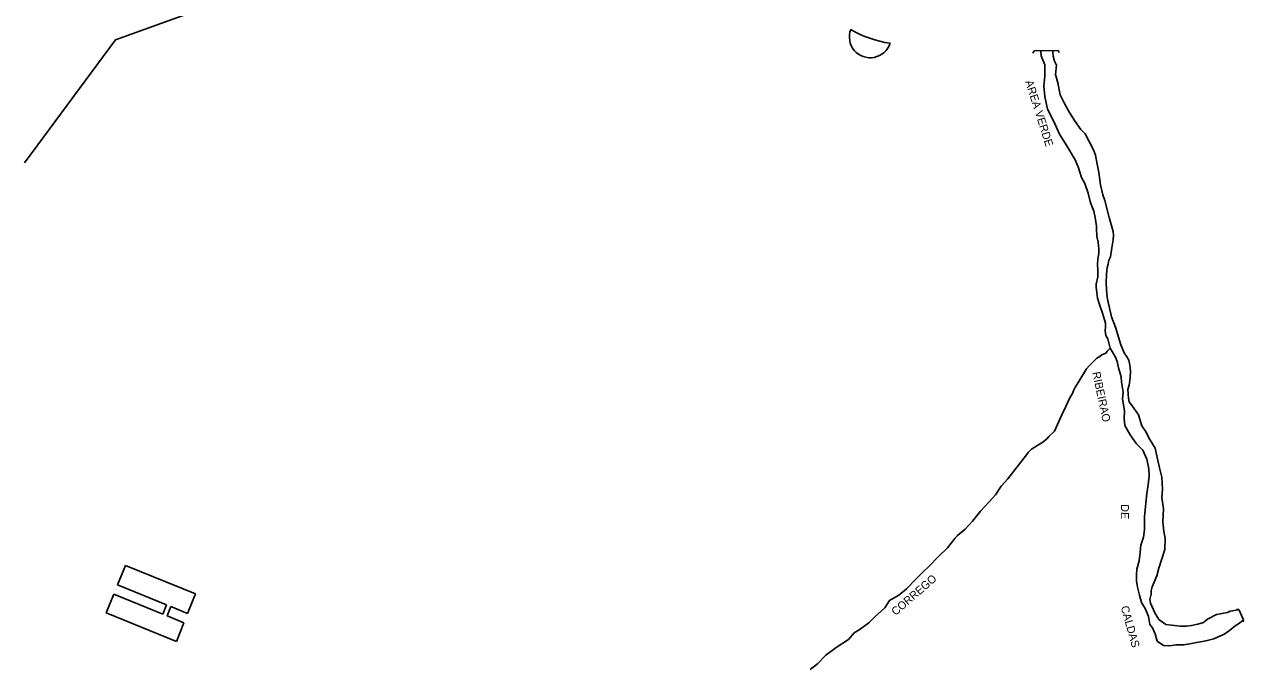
# Model space of a CAD drawing. Extents: x 325899 to 363134, y 7578590 to 7592502.
# Drawn here: x 338159 to 338768, y 7587778 to 7588098 of the extents above; entities that cross this region are included whole.
import ezdxf

# ---------------------------------------------------------------- set-up
doc = ezdxf.new("R2010")
doc.units = 0
for name, color, linetype in [('EDIFEXISTENT', 7, 'Continuous'), ('EDIFIDENTIF', 7, 'Continuous'), ('EDIFOBRAEXIS', 7, 'Continuous')]:
    doc.layers.add(name, color=color, linetype=linetype)

msp = doc.modelspace()

# ---------------------------------------------------------------- linework, layer by layer
at = {"layer": 'EDIFEXISTENT'}
for p, q in [((338662.44, 7588083.88), (338663.12, 7588085.07)), ((338663.12, 7588085.07), (338675.13, 7588085.24)), ((338675.13, 7588085.24), (338675.69, 7588084.26)), ((338205.07, 7587818.35), (338209.08, 7587828.1)), ((338209.08, 7587828.1), (338244.06, 7587813.85)), ((338199.38, 7587804.47), (338203.16, 7587813.75)), ((338203.16, 7587813.75), (338227.69, 7587803.76)), ((338229.57, 7587808.37), (338205.07, 7587818.35)), ((338244.06, 7587813.85), (338240.08, 7587804.1)), ((338227.69, 7587803.76), (338229.57, 7587808.37)), ((338231.72, 7587807.51), (338229.82, 7587802.85)), ((338240.08, 7587804.1), (338231.72, 7587807.51)), ((338234.5, 7587790.16), (338199.38, 7587804.47)), ((338229.82, 7587802.85), (338238.27, 7587799.41)), ((338764.43, 7587806.26), (338765.47, 7587806.07)), ((338765.47, 7587806.07), (338767.81, 7587800.88)), ((338238.27, 7587799.41), (338234.5, 7587790.16)), ((338767.81, 7587800.88), (338767.49, 7587799.99))]:
    msp.add_line(p, q, dxfattribs=at)
at = {"layer": 'EDIFOBRAEXIS'}
for points in [[(338481.39, 7588190.13), (338471.26, 7588198.35), (338470.08, 7588196.82), (338459.91, 7588204.12), (338445.71, 7588204.19), (338414.48, 7588196.06), (338360.86, 7588147.14), (338204.04, 7588090.5), (338158.53, 7588029.1)], [(338666.51, 7588085.05), (338666.58, 7588082.49), (338668.52, 7588078), (338668.41, 7588072.4), (338667.97, 7588067.35), (338668.41, 7588062.26), (338669.88, 7588055.92), (338673.15, 7588049.43), (338675.73, 7588043.45), (338679.43, 7588037.7), (338683.64, 7588030.56), (338685.36, 7588026.65), (338686.75, 7588021.82), (338688.49, 7588018.9), (338690.13, 7588013.92), (338691.1, 7588009.85), (338691.98, 7588007.5), (338692.93, 7588005.02), (338693.61, 7588001.91)], [(338700.67, 7588001.91), (338698.52, 7588010.31), (338697.43, 7588013.09), (338696.35, 7588018.07), (338695.98, 7588020.7), (338695.49, 7588024.37), (338694.62, 7588028.55), (338693.85, 7588033), (338692.87, 7588035.7), (338690.68, 7588039.71), (338688.58, 7588043.67), (338686.41, 7588045.73), (338683.36, 7588050.27), (338680.35, 7588055.16), (338678.14, 7588059.02), (338676.14, 7588063.11), (338674.95, 7588069.03), (338673.83, 7588073.28), (338674.25, 7588077.94), (338673.34, 7588079.86), (338672.61, 7588082.41), (338672.4, 7588084.34), (338672.31, 7588085.22)], [(338551.28, 7587776.1), (338554.84, 7587779.01), (338559.05, 7587783.25), (338564.2, 7587787.03), (338570.36, 7587791.13), (338573.13, 7587794.39), (338576.24, 7587796.32), (338580.56, 7587799.46), (338583.46, 7587802.42), (338588.58, 7587806.84), (338590.91, 7587810.61), (338595.56, 7587813.2), (338599.37, 7587816.35), (338604.16, 7587821.42), (338607.56, 7587824.77), (338610.72, 7587827.65), (338615.25, 7587832.3), (338619.82, 7587836.94), (338623.44, 7587841.56), (338624.88, 7587843.06), (338628.71, 7587846.18), (338632.29, 7587850.16), (338636.29, 7587855.2), (338640.65, 7587859.77), (338643.8, 7587863.27), (338646.64, 7587867.67), (338650.04, 7587871.4), (338658.09, 7587881.9), (338659.25, 7587883.38), (338660.13, 7587884.52), (338661.74, 7587886.1), (338663.96, 7587887.46), (338665.03, 7587888.13), (338667.43, 7587889.69), (338669.47, 7587891.35), (338670.43, 7587892.4), (338673.38, 7587895.21), (338676.23, 7587901.72), (338676.98, 7587903.32), (338678.98, 7587907.44), (338679.78, 7587909.25), (338681.08, 7587912.1), (338682.24, 7587913.96), (338682.99, 7587915.74), (338683.49, 7587916.8), (338685.4, 7587919.94), (338689.37, 7587926.22), (338690.55, 7587927.83), (338692.84, 7587929.95), (338694.41, 7587931.61), (338696.07, 7587932.58), (338697.01, 7587933.22), (338699.03, 7587934.17), (338699.58, 7587935.06), (338701.15, 7587936.62), (338699.88, 7587941.23), (338698.98, 7587942.85), (338698.63, 7587945.2), (338698.82, 7587947.29), (338698.81, 7587949.09), (338698.01, 7587951.92), (338697.18, 7587954.58), (338696.04, 7587957.92), (338694.8, 7587961.62), (338694.16, 7587967.01), (338694.2, 7587968.61), (338694.94, 7587972.22), (338694.99, 7587975.8), (338694.8, 7587978.23), (338694.98, 7587981.22), (338695.5, 7587983.79), (338695.41, 7587986.24), (338695.06, 7587989.52), (338694.54, 7587992.28), (338694.5, 7587993.24), (338694.31, 7587995.58), (338694.3, 7587997.45), (338693.61, 7588001.91)], [(338700.67, 7588001.91), (338702.68, 7587994.86), (338702.83, 7587992.86), (338702.61, 7587990.66), (338701.93, 7587986.62), (338701.27, 7587982.25), (338700.49, 7587980.47), (338700.1, 7587978.57), (338699.63, 7587976.92), (338699.24, 7587973.72), (338699.17, 7587968.64), (338699.41, 7587963.57), (338699.85, 7587961.06), (338701.81, 7587952.25), (338703.8, 7587947.09), (338706.51, 7587938.25), (338708.29, 7587933.95), (338709.26, 7587932.64), (338710.39, 7587930.67), (338710.99, 7587928.06), (338711.34, 7587925.17), (338711.18, 7587921.77), (338710.65, 7587918.19), (338710.03, 7587915.95), (338710.33, 7587911.69), (338710.55, 7587909.82), (338713.03, 7587906.69), (338715.36, 7587903.33), (338717.01, 7587897.74), (338718.8, 7587895.13), (338720.91, 7587890.91), (338723.65, 7587886.69), (338724.91, 7587880.56), (338725.74, 7587876.86), (338726.91, 7587872.15), (338727.28, 7587866.17), (338726.87, 7587861.98), (338727.82, 7587856.38), (338727.36, 7587849.81), (338728.02, 7587845.1), (338728.6, 7587841.7), (338728.48, 7587836.1), (338726.99, 7587831.39), (338725.5, 7587826.64), (338724.5, 7587822.91), (338722.18, 7587817.41), (338721.56, 7587815.48), (338721.67, 7587813.71), (338720.93, 7587811.09), (338721.32, 7587809.24), (338723.5, 7587804.44), (338725.5, 7587801.13), (338729.02, 7587798.59), (338731.79, 7587798.2), (338736.18, 7587797.82), (338739.25, 7587797.81), (338741.75, 7587798.16), (338744.85, 7587798.68), (338747.73, 7587799.67), (338749.78, 7587801.23), (338754.33, 7587803.61), (338759.72, 7587804.53), (338760.1, 7587804.69), (338761.14, 7587805.2), (338762.2, 7587805.34), (338764.03, 7587805.68), (338765.47, 7587806.07)], [(338767.81, 7587800.88), (338765.82, 7587799.22), (338763.67, 7587797.91), (338760.77, 7587795.66), (338757.86, 7587793.62), (338756.19, 7587792.95), (338752.88, 7587791.35), (338749.61, 7587790.57), (338747.26, 7587790.1), (338744.34, 7587789.68), (338740.9, 7587788.89), (338737.88, 7587788.47), (338734.18, 7587788.45), (338730.99, 7587787.92), (338727.74, 7587788.18), (338724.58, 7587790.34), (338723.59, 7587793.96), (338722.23, 7587796.97), (338721, 7587798.56), (338720.27, 7587802.59), (338719.6, 7587804.31), (338718.65, 7587806.59), (338716.72, 7587809.52), (338715.81, 7587813.29), (338714.77, 7587817.27), (338714.3, 7587820.23), (338714.28, 7587823.22), (338714.44, 7587826.22), (338715.58, 7587830.46), (338716.06, 7587834.52), (338716.47, 7587838.13), (338717.71, 7587842.12), (338718.35, 7587846.05), (338718.26, 7587852.37), (338718.57, 7587855.84), (338718.9, 7587859.14), (338719.38, 7587863.94), (338720.19, 7587868.38), (338720.54, 7587872.75), (338720.49, 7587876.3), (338719.42, 7587881.11), (338717.47, 7587885.69), (338714.25, 7587888.84), (338711.06, 7587893.26), (338708.49, 7587897.94), (338708.16, 7587901.43), (338708.29, 7587905.29), (338707.34, 7587911.04), (338707.7, 7587914.65), (338706.81, 7587919.56), (338706.66, 7587922.35), (338705.37, 7587926.78), (338704.61, 7587929.95), (338703.81, 7587932.12), (338701.15, 7587936.62)]]:
    msp.add_lwpolyline(points, dxfattribs=at)
for centre, radius, start, end in [((338581.22, 7588092.03), 10.42, 159.17322, 342.11868), ((338598.66, 7588141.67), 53.36, 239.39258, 261.89932)]:
    msp.add_arc(centre, radius, start, end, dxfattribs=at)

# ---------------------------------------------------------------- texts
at = {"layer": 'EDIFIDENTIF'}
for s, rotation, p in [('AREA VERDE', 287.5621, (338658.61, 7588069.74)), ('RIBEIRAO', 282.01179, (338692.16, 7587924.4)), ('DE', 269.13441, (338706.56, 7587858.67)), ('CORREGO', 40.8926, (338593.91, 7587802.81)), ('CALDAS', 285.75829, (338706.35, 7587807.31))]:
    msp.add_text(s, height=4, rotation=rotation, dxfattribs=at).set_placement(p)

doc.saveas('drawing.dxf')
